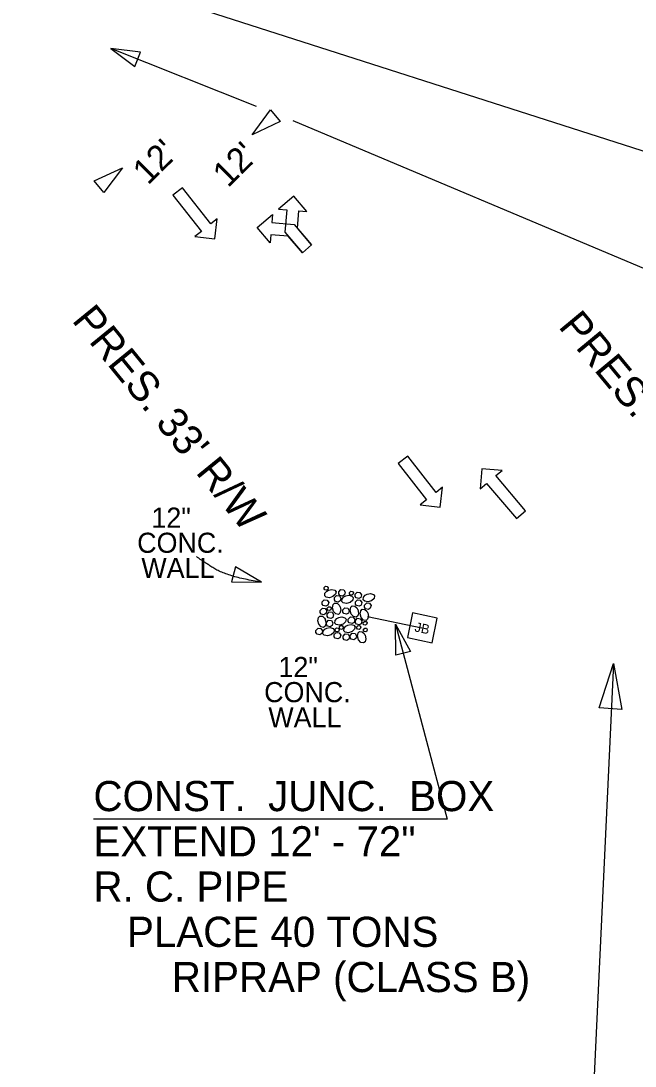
# Model space of a CAD drawing. Extents: x 16382402 to 16388022, y 46194326 to 46202918.
# Drawn here: x 16385047.9 to 16385170.1, y 46194798.9 to 46195006.8 of the extents above; entities that cross this region are included whole.
import ezdxf

# ---------------------------------------------------------------- set-up
doc = ezdxf.new("R2010")
doc.units = 0
for name, color, linetype in [('RD_EX_DR_Inlet', 7, 'Continuous'), ('RD_EX_RW_TX', 7, 'Continuous'), ('RD_HC_Data', 7, 'Continuous'), ('RD_PD_Final_LnLine', 7, 'Continuous'), ('RD_PD_Final_TX', 7, 'Continuous'), ('RD_TX_Bldg', 7, 'Continuous'), ('RD_TX_Drainage', 7, 'Continuous')]:
    doc.layers.add(name, color=color, linetype=linetype)

msp = doc.modelspace()

# ---------------------------------------------------------------- linework, layer by layer
at = {"layer": 'RD_EX_DR_Inlet'}
msp.add_line((16385129.73, 46194883.1), (16385130.74, 46194888), dxfattribs=at)
msp.add_lwpolyline([(16385129.73, 46194883.1), (16385130.74, 46194888), (16385125.84, 46194889.01), (16385124.83, 46194884.12)], close=True, dxfattribs=at)
at = {"layer": 'RD_HC_Data'}
msp.add_line((16385165.83, 46194878.95), (16385156.24, 46194673.58), dxfattribs=at)
at = {"layer": 'RD_PD_Final_LnLine'}
for points in [[(16385080.01, 46194973.62), (16385078.12, 46194972.14), (16385083.78, 46194964.92), (16385082.5, 46194963.91), (16385086.47, 46194963.43), (16385086.95, 46194967.4), (16385085.67, 46194966.4)], [(16385103.89, 46194960.67), (16385105.72, 46194962.22), (16385102.89, 46194965.55), (16385103.19, 46194969.02), (16385104.81, 46194968.88), (16385102.22, 46194971.93), (16385099.17, 46194969.34), (16385100.79, 46194969.21), (16385100.43, 46194964.74)], [(16385105.72, 46194962.22), (16385103.89, 46194960.67), (16385101.06, 46194964), (16385097.59, 46194964.27), (16385097.46, 46194962.64), (16385094.87, 46194965.69), (16385097.92, 46194968.28), (16385097.79, 46194966.66), (16385102.25, 46194966.29)], [(16385124.86, 46194920.22), (16385122.97, 46194918.74), (16385128.62, 46194911.52), (16385127.34, 46194910.52), (16385131.31, 46194910.04), (16385131.8, 46194914.01), (16385130.51, 46194913)], [(16385146.5, 46194907.8), (16385148.33, 46194909.35), (16385142.39, 46194916.34), (16385143.64, 46194917.39), (16385139.65, 46194917.72), (16385139.32, 46194913.73), (16385140.57, 46194914.79)]]:
    msp.add_lwpolyline(points, close=True, dxfattribs=at)
at = {"layer": 'RD_PD_Final_TX'}
msp.add_line((16385240.85, 46194958.73), (16385047.85, 46195020.61), dxfattribs=at)
for points in [[(16385108.26, 46194894.07), (16385108.52, 46194894.33), (16385108.85, 46194894.29), (16385109.04, 46194894.01), (16385108.95, 46194893.69), (16385108.71, 46194893.55), (16385108.39, 46194893.63), (16385108.26, 46194893.81), (16385108.26, 46194894.07)], [(16385109.09, 46194893.54), (16385109.78, 46194893.68), (16385110.36, 46194893.52), (16385110.59, 46194893.21), (16385110.5, 46194892.73), (16385109.98, 46194892.26), (16385109.26, 46194892.04), (16385108.63, 46194892.14), (16385108.33, 46194892.45), (16385108.38, 46194892.95), (16385108.74, 46194893.35), (16385109.12, 46194893.55)], [(16385111.14, 46194893.24), (16385111.57, 46194893.67), (16385112.13, 46194893.6), (16385112.44, 46194893.14), (16385112.29, 46194892.59), (16385111.9, 46194892.37), (16385111.36, 46194892.51), (16385111.15, 46194892.8), (16385111.14, 46194893.24)], [(16385113.27, 46194893.07), (16385113.53, 46194893.33), (16385113.86, 46194893.29), (16385114.05, 46194893.01), (16385113.96, 46194892.68), (16385113.72, 46194892.55), (16385113.4, 46194892.63), (16385113.27, 46194892.81), (16385113.27, 46194893.07)], [(16385114.38, 46194892.74), (16385114.81, 46194893.17), (16385115.36, 46194893.11), (16385115.68, 46194892.64), (16385115.52, 46194892.1), (16385115.13, 46194891.87), (16385114.6, 46194892.01), (16385114.38, 46194892.3), (16385114.38, 46194892.74)], [(16385116.76, 46194892.73), (16385117.45, 46194892.87), (16385118.03, 46194892.71), (16385118.27, 46194892.4), (16385118.17, 46194891.92), (16385117.65, 46194891.45), (16385116.93, 46194891.23), (16385116.31, 46194891.33), (16385116, 46194891.64), (16385116.05, 46194892.14), (16385116.42, 46194892.54), (16385116.79, 46194892.74)], [(16385107.83, 46194891.22), (16385108.26, 46194891.65), (16385108.82, 46194891.58), (16385109.13, 46194891.12), (16385108.98, 46194890.57), (16385108.59, 46194890.35), (16385108.05, 46194890.48), (16385107.84, 46194890.78), (16385107.83, 46194891.22)], [(16385111.39, 46194890.23), (16385111.53, 46194889.54), (16385111.38, 46194888.96), (16385111.06, 46194888.72), (16385110.58, 46194888.82), (16385110.11, 46194889.34), (16385109.9, 46194890.06), (16385110, 46194890.68), (16385110.31, 46194890.99), (16385110.81, 46194890.94), (16385111.2, 46194890.57), (16385111.4, 46194890.2)], [(16385110.26, 46194892.06), (16385110.69, 46194892.49), (16385111.25, 46194892.42), (16385111.56, 46194891.96), (16385111.41, 46194891.41), (16385111.02, 46194891.19), (16385110.48, 46194891.32), (16385110.27, 46194891.62), (16385110.26, 46194892.06)], [(16385112.5, 46194892.4), (16385113.19, 46194892.54), (16385113.77, 46194892.38), (16385114.01, 46194892.06), (16385113.91, 46194891.59), (16385113.39, 46194891.11), (16385112.67, 46194890.9), (16385112.04, 46194891), (16385111.74, 46194891.31), (16385111.79, 46194891.81), (16385112.16, 46194892.21), (16385112.53, 46194892.41)], [(16385114.44, 46194891.22), (16385114.87, 46194891.65), (16385115.43, 46194891.58), (16385115.74, 46194891.12), (16385115.59, 46194890.57), (16385115.2, 46194890.35), (16385114.66, 46194890.48), (16385114.45, 46194890.78), (16385114.44, 46194891.22)], [(16385116.27, 46194890.58), (16385116.7, 46194891.01), (16385117.26, 46194890.95), (16385117.57, 46194890.48), (16385117.42, 46194889.94), (16385117.03, 46194889.71), (16385116.49, 46194889.85), (16385116.28, 46194890.14), (16385116.27, 46194890.58)], [(16385107.44, 46194889.53), (16385107.87, 46194889.96), (16385108.42, 46194889.89), (16385108.74, 46194889.43), (16385108.58, 46194888.88), (16385108.19, 46194888.66), (16385107.66, 46194888.8), (16385107.44, 46194889.09), (16385107.44, 46194889.53)], [(16385108.81, 46194888.79), (16385109.24, 46194889.22), (16385109.79, 46194889.15), (16385110.11, 46194888.69), (16385109.95, 46194888.14), (16385109.56, 46194887.92), (16385109.03, 46194888.05), (16385108.81, 46194888.35), (16385108.81, 46194888.79)], [(16385108.84, 46194890), (16385109.1, 46194890.26), (16385109.43, 46194890.22), (16385109.62, 46194889.94), (16385109.53, 46194889.61), (16385109.29, 46194889.48), (16385108.97, 46194889.56), (16385108.85, 46194889.74), (16385108.84, 46194890)], [(16385111.92, 46194889.63), (16385112.36, 46194890.06), (16385112.91, 46194890), (16385113.22, 46194889.53), (16385113.07, 46194888.99), (16385112.68, 46194888.76), (16385112.14, 46194888.9), (16385111.93, 46194889.19), (16385111.92, 46194889.63)], [(16385114.91, 46194889.69), (16385115.05, 46194889), (16385114.9, 46194888.42), (16385114.58, 46194888.19), (16385114.1, 46194888.28), (16385113.63, 46194888.8), (16385113.42, 46194889.52), (16385113.51, 46194890.15), (16385113.83, 46194890.45), (16385114.33, 46194890.4), (16385114.72, 46194890.04), (16385114.92, 46194889.67)], [(16385116.9, 46194889.02), (16385117.04, 46194888.33), (16385116.89, 46194887.75), (16385116.57, 46194887.51), (16385116.09, 46194887.61), (16385115.62, 46194888.13), (16385115.4, 46194888.85), (16385115.5, 46194889.47), (16385115.81, 46194889.78), (16385116.32, 46194889.73), (16385116.71, 46194889.36), (16385116.91, 46194888.99)], [(16385108.46, 46194887.65), (16385108.6, 46194886.96), (16385108.45, 46194886.38), (16385108.13, 46194886.14), (16385107.65, 46194886.24), (16385107.18, 46194886.76), (16385106.97, 46194887.48), (16385107.07, 46194888.1), (16385107.38, 46194888.41), (16385107.88, 46194888.36), (16385108.27, 46194887.99), (16385108.47, 46194887.62)], [(16385108.67, 46194887.15), (16385109.11, 46194887.57), (16385109.66, 46194887.51), (16385109.97, 46194887.04), (16385109.82, 46194886.5), (16385109.43, 46194886.28), (16385108.89, 46194886.41), (16385108.68, 46194886.7), (16385108.67, 46194887.15)], [(16385111.09, 46194888.09), (16385111.78, 46194888.23), (16385112.36, 46194888.07), (16385112.6, 46194887.75), (16385112.5, 46194887.27), (16385111.98, 46194886.8), (16385111.26, 46194886.59), (16385110.64, 46194886.69), (16385110.33, 46194887), (16385110.39, 46194887.5), (16385110.75, 46194887.89), (16385111.12, 46194888.1)], [(16385111.25, 46194886.28), (16385111.51, 46194886.53), (16385111.84, 46194886.49), (16385112.03, 46194886.21), (16385111.94, 46194885.89), (16385111.7, 46194885.75), (16385111.38, 46194885.83), (16385111.25, 46194886.01), (16385111.25, 46194886.28)], [(16385112.89, 46194886.58), (16385113.58, 46194886.72), (16385114.16, 46194886.56), (16385114.4, 46194886.25), (16385114.3, 46194885.77), (16385113.78, 46194885.3), (16385113.06, 46194885.08), (16385112.43, 46194885.18), (16385112.13, 46194885.49), (16385112.18, 46194886), (16385112.55, 46194886.39), (16385112.92, 46194886.59)], [(16385113.02, 46194887.79), (16385113.45, 46194888.22), (16385114.01, 46194888.15), (16385114.32, 46194887.69), (16385114.17, 46194887.14), (16385113.78, 46194886.92), (16385113.24, 46194887.06), (16385113.03, 46194887.35), (16385113.02, 46194887.79)], [(16385114.44, 46194887.52), (16385114.87, 46194887.95), (16385115.42, 46194887.88), (16385115.74, 46194887.42), (16385115.58, 46194886.87), (16385115.19, 46194886.65), (16385114.66, 46194886.78), (16385114.44, 46194887.08), (16385114.44, 46194887.52)], [(16385114.73, 46194886.24), (16385114.99, 46194886.5), (16385115.32, 46194886.46), (16385115.51, 46194886.18), (16385115.42, 46194885.86), (16385115.18, 46194885.72), (16385114.86, 46194885.8), (16385114.73, 46194885.98), (16385114.73, 46194886.24)], [(16385115.98, 46194887.09), (16385116.24, 46194887.35), (16385116.57, 46194887.31), (16385116.76, 46194887.03), (16385116.67, 46194886.7), (16385116.43, 46194886.57), (16385116.11, 46194886.65), (16385115.98, 46194886.82), (16385115.98, 46194887.09)], [(16385106.59, 46194885.56), (16385107.02, 46194885.99), (16385107.58, 46194885.92), (16385107.89, 46194885.46), (16385107.74, 46194884.91), (16385107.35, 46194884.69), (16385106.81, 46194884.82), (16385106.6, 46194885.12), (16385106.59, 46194885.56)], [(16385108.71, 46194885.96), (16385109.4, 46194886.1), (16385109.99, 46194885.95), (16385110.22, 46194885.63), (16385110.13, 46194885.15), (16385109.6, 46194884.68), (16385108.89, 46194884.47), (16385108.26, 46194884.57), (16385107.95, 46194884.88), (16385108.01, 46194885.38), (16385108.37, 46194885.77), (16385108.74, 46194885.97)], [(16385110.22, 46194884.73), (16385110.65, 46194885.16), (16385111.21, 46194885.09), (16385111.52, 46194884.63), (16385111.36, 46194884.08), (16385110.97, 46194883.86), (16385110.44, 46194883.99), (16385110.23, 46194884.29), (16385110.22, 46194884.73)], [(16385110.43, 46194885.8), (16385110.69, 46194886.06), (16385111.02, 46194886.02), (16385111.21, 46194885.74), (16385111.12, 46194885.41), (16385110.89, 46194885.28), (16385110.56, 46194885.36), (16385110.44, 46194885.54), (16385110.43, 46194885.8)], [(16385112, 46194884.43), (16385112.43, 46194884.86), (16385112.99, 46194884.8), (16385113.3, 46194884.33), (16385113.15, 46194883.79), (16385112.76, 46194883.56), (16385112.22, 46194883.7), (16385112.01, 46194883.99), (16385112, 46194884.43)], [(16385113.4, 46194884.56), (16385113.83, 46194884.99), (16385114.39, 46194884.92), (16385114.7, 46194884.46), (16385114.55, 46194883.91), (16385114.16, 46194883.69), (16385113.62, 46194883.82), (16385113.41, 46194884.12), (16385113.4, 46194884.56)], [(16385116.37, 46194884.57), (16385116.51, 46194883.88), (16385116.36, 46194883.3), (16385116.04, 46194883.07), (16385115.56, 46194883.16), (16385115.09, 46194883.68), (16385114.88, 46194884.4), (16385114.98, 46194885.03), (16385115.29, 46194885.33), (16385115.79, 46194885.28), (16385116.18, 46194884.92), (16385116.38, 46194884.55)], [(16385116.04, 46194885.76), (16385116.3, 46194886.02), (16385116.64, 46194885.98), (16385116.82, 46194885.7), (16385116.73, 46194885.37), (16385116.5, 46194885.24), (16385116.18, 46194885.32), (16385116.05, 46194885.5), (16385116.04, 46194885.76)]]:
    msp.add_lwpolyline(points, dxfattribs=at)
at = {"layer": 'RD_TX_Bldg'}
msp.add_open_spline([(16385095.78, 46194895.16), (16385088.78, 46194896.18), (16385082.82, 46194900.19), (16385082.82, 46194900.19)], degree=2, dxfattribs=at)
at = {"layer": 'RD_TX_Drainage'}
for p, q in [((16385094.77, 46194989.8), (16385065.74, 46195001.33)), ((16385263.51, 46194918.95), (16385102.03, 46194986.91)), ((16385127.65, 46194886), (16385116.88, 46194888.23)), ((16385122.44, 46194886.8), (16385132.69, 46194847.97)), ((16385129.73, 46194883.1), (16385130.74, 46194888)), ((16385132.69, 46194847.97), (16385062.3, 46194847.97))]:
    msp.add_line(p, q, dxfattribs=at)
for points in [[(16385071.69, 46195000.58), (16385065.74, 46195001.33), (16385070.51, 46194997.7)], [(16385099.44, 46194986.8), (16385093.87, 46194984.11), (16385097.52, 46194989.1)], [(16385062.47, 46194974.95), (16385068.06, 46194977.59), (16385064.37, 46194972.63)], [(16385089.78, 46194895.18), (16385095.78, 46194895.16), (16385090.59, 46194898.18)], [(16385129.73, 46194883.1), (16385130.74, 46194888), (16385125.84, 46194889.01), (16385124.83, 46194884.12)], [(16385122.52, 46194880.62), (16385122.44, 46194886.8), (16385125.42, 46194881.38)], [(16385163, 46194870.11), (16385165.83, 46194878.95), (16385167.49, 46194869.82)]]:
    msp.add_lwpolyline(points, close=True, dxfattribs=at)

# ---------------------------------------------------------------- texts
at = {"layer": 'RD_EX_DR_Inlet'}
msp.add_text('JB', height=1.875, rotation=348.3223, dxfattribs=at).set_placement((16385126.14, 46194885.36))
at = {"layer": 'RD_EX_RW_TX'}
for rotation, p in [(309.1965, (16385057.85, 46194947.17)), (309.6469, (16385154.7, 46194945.94))]:
    msp.add_text("PRES. 33' R/W ", height=6, rotation=rotation, dxfattribs=at).set_placement(p)
at = {"layer": 'RD_PD_Final_TX'}
for p in [(16385073.14, 46194974), (16385089.06, 46194973.47)]:
    msp.add_text("12'", height=5, rotation=44.5475, dxfattribs=at).set_placement(p)
at = {"layer": 'RD_TX_Bldg'}
for s, p in [('12"', (16385073.84, 46194905.98)), ('CONC.', (16385071, 46194900.98)), ('WALL', (16385071.83, 46194895.98)), ('12"', (16385099.13, 46194876.27)), ('CONC.', (16385096.28, 46194871.27)), ('WALL', (16385097.11, 46194866.27))]:
    msp.add_text(s, height=4, rotation=360, dxfattribs=at).set_placement(p)
at = {"layer": 'RD_TX_Drainage'}
msp.add_text('JB', height=1.875, rotation=348.3223, dxfattribs=at).set_placement((16385126.14, 46194885.36))
for s, p in [('CONST.  JUNC.  BOX', (16385062.3, 46194849.59)), ('EXTEND 12\' - 72" ', (16385062.3, 46194840.59)), ('R. C. PIPE', (16385062.3, 46194831.59)), ('   PLACE 40 TONS ', (16385062.3, 46194822.59)), ('       RIPRAP (CLASS B)', (16385062.3, 46194813.59))]:
    msp.add_text(s, height=6, dxfattribs=at).set_placement(p)

doc.saveas('drawing.dxf')
